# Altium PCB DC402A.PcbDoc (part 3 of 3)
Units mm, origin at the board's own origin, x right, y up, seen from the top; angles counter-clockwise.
Board outline 93 x 73 mm, 4 copper layers (Top Layer, Int1 (GND), Int2 (PWR), Bottom Layer), stack 1.369 mm thick; 244 components, 141 nets, 575 pads, 306 vias.
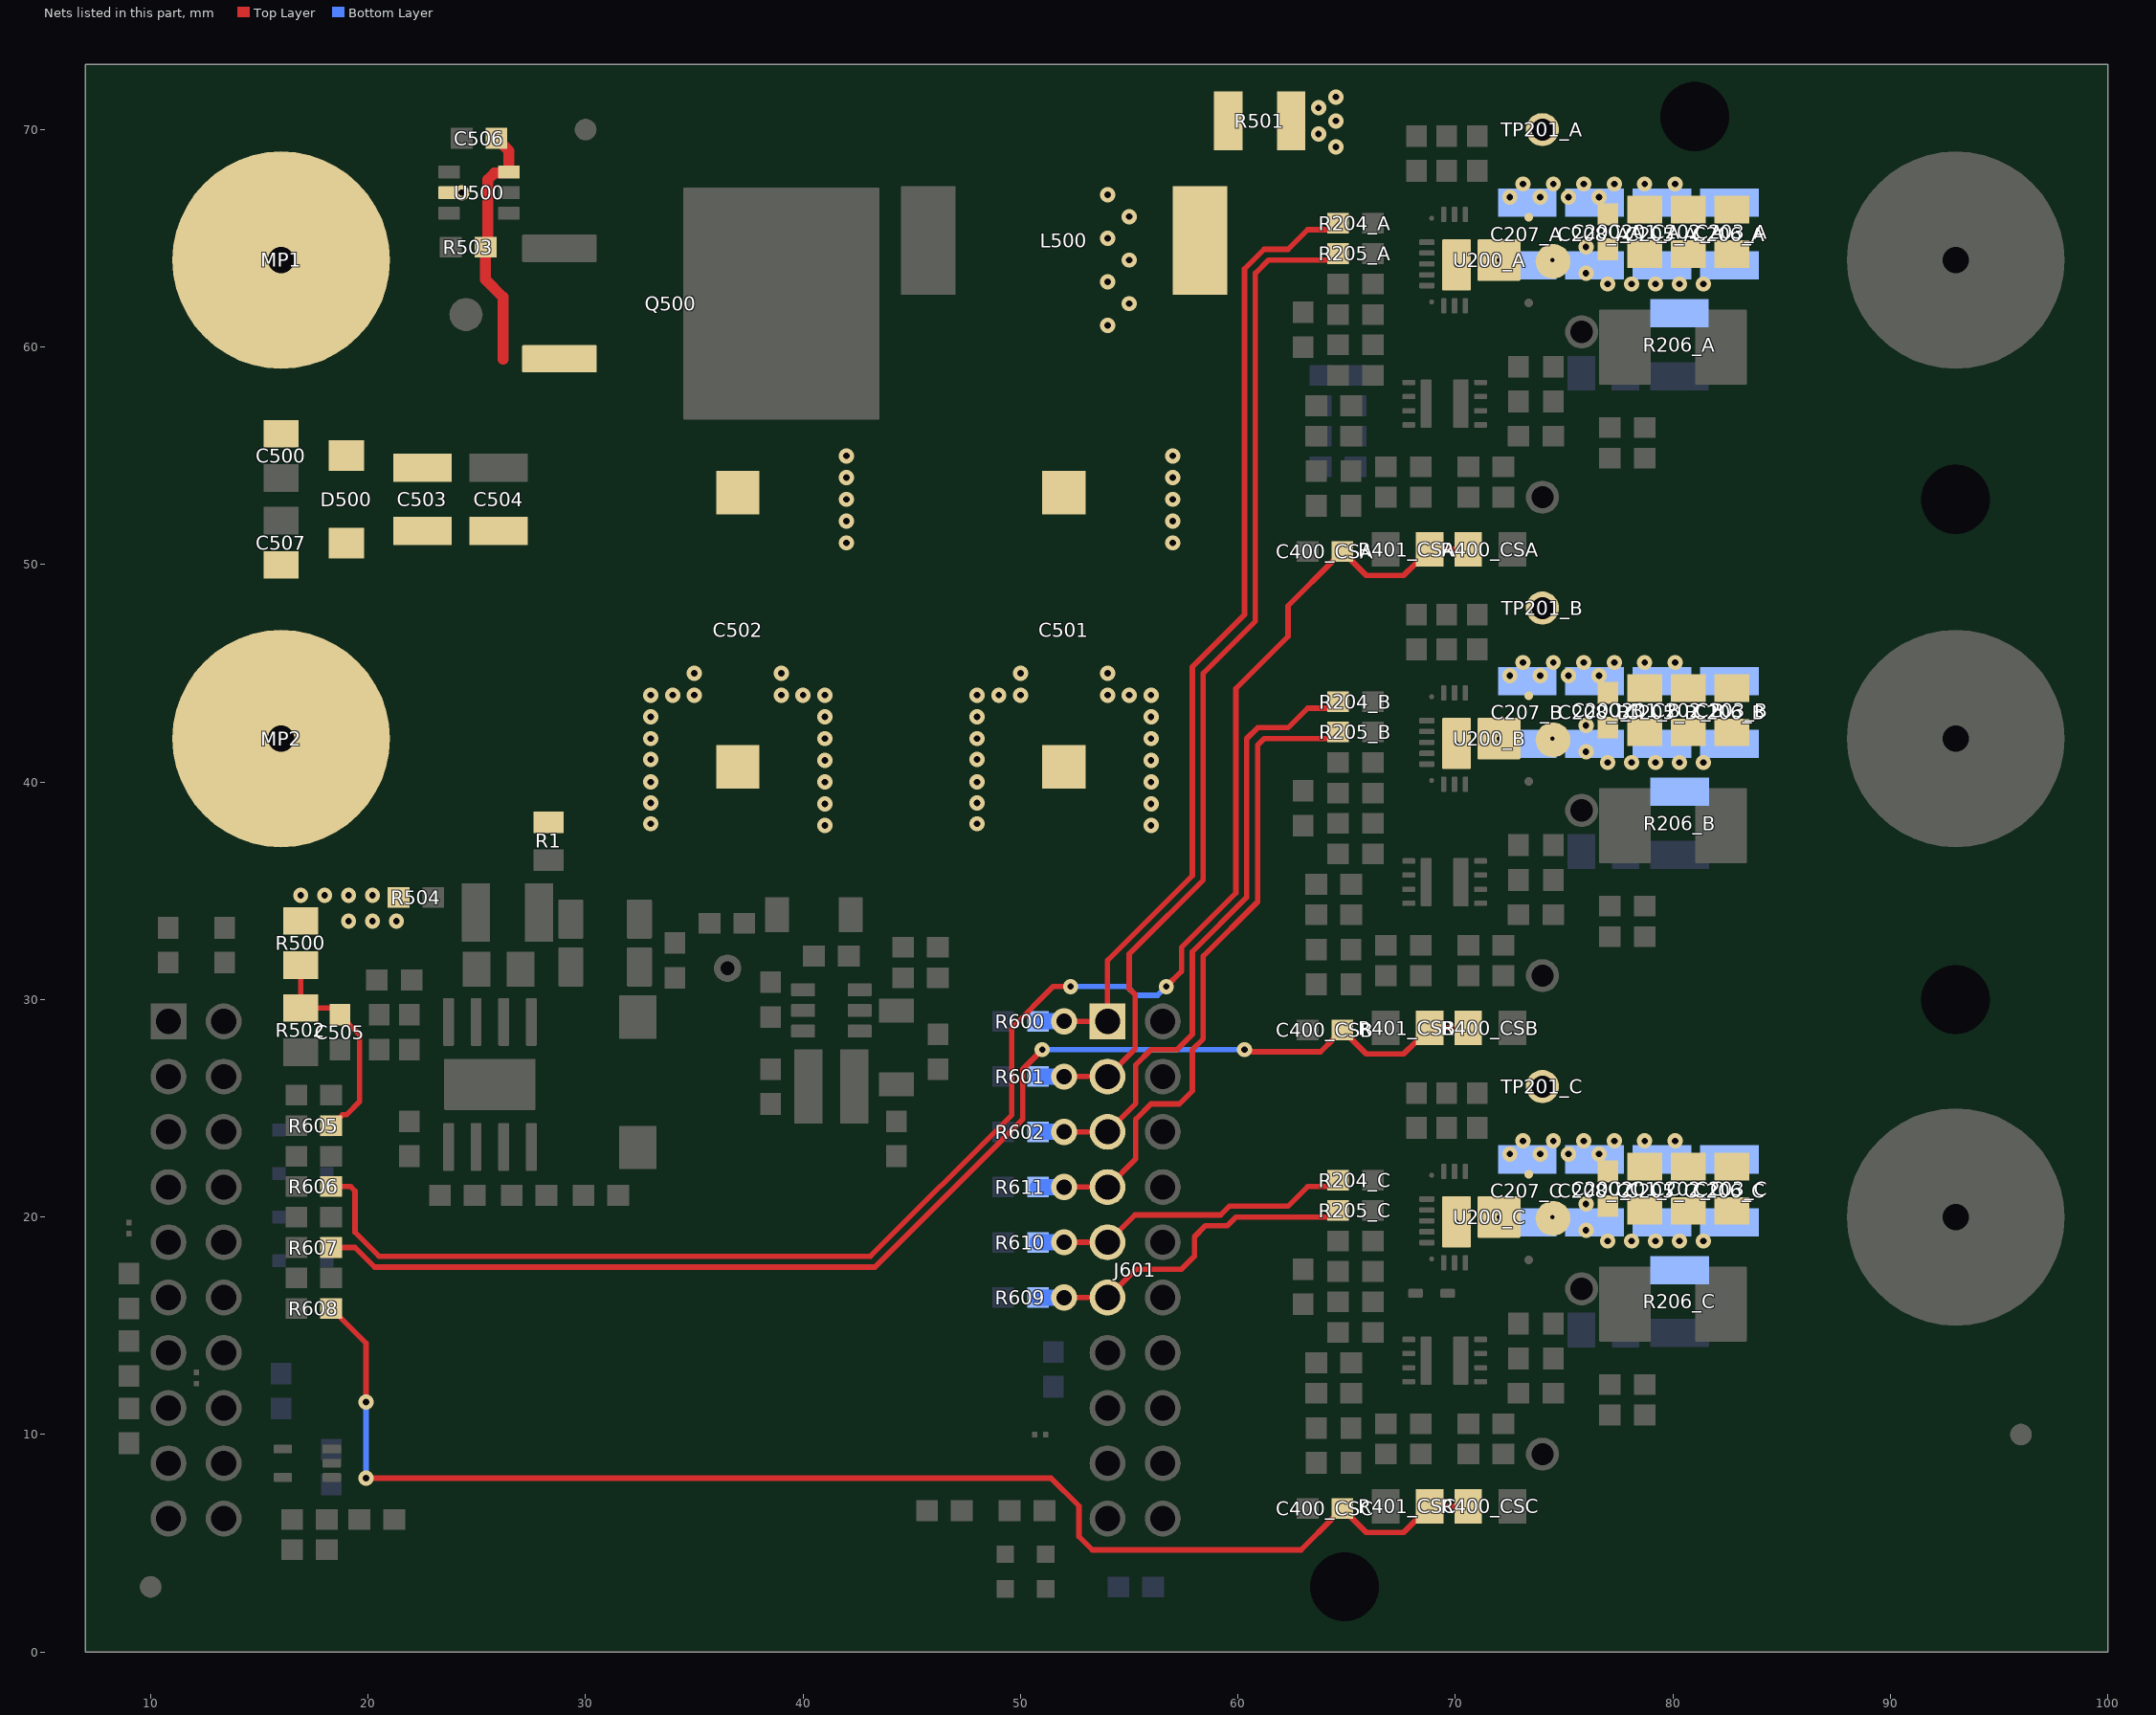
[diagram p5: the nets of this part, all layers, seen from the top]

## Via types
v1: diameter 0.7, hole 0.3, Top Layer to Bottom Layer, tented both sides, 277 vias
v2: diameter 1.2, hole 0.7, Top Layer to Bottom Layer, 10 vias
v3: diameter 0.5, hole 0.2, Top Layer to Bottom Layer, tented both sides, 9 vias
v4: diameter 0.7, hole 0.3, Top Layer to Bottom Layer, 9 vias
v5: diameter 1.2, hole 0.7, Top Layer to Bottom Layer, tented bottom, 1 vias

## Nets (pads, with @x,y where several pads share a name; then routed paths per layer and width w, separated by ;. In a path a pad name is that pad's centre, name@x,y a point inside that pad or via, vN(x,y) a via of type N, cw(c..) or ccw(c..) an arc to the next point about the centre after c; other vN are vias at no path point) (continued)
PGND: C200_A.2 C200_B.2 C200_C.2 C201_A.2 C201_B.2 C201_C.2 C202_A.2 C202_B.2 C202_C.2 C203_A.2 C203_B.2 C203_C.2 C205_A.2 C205_B.2 C205_C.2 C206_A.2 C206_B.2 C206_C.2 C207_A.2 C207_B.2 C207_C.2 C208_A.2 C208_B.2 C208_C.2 C501.2 C502.2 C503.2 C504.2 C507.2 D500.1 MP2.1 R1.1 R206_A.1 R206_B.1 R206_C.1 R501.1 TP201_A.1 TP201_B.1 TP201_C.1 U200_A.6 U200_B.6 U200_C.6 U500.2 | length 0.6
  Top Layer w0.5: U500.2@23.725,67.1 v1(24.3,67.1)
  other v1: 77,18.9 78.1,18.9 79.2,18.9 80.3,18.9 81.4,18.9 76,19.4 76,20.6 41,38 56,38 33,38.084 48,38.084 41,39 56,39 33,39.042 48,39.042 33,40 41,40 48,40 56,40 77,40.9 78.1,40.9 79.2,40.9 80.3,40.9 81.4,40.9 41,41 56,41 33,41.042 48,41.042 76,41.4 33,42 41,42 48,42 56,42 76,42.6 33,43 41,43 48,43 56,43 33,44 34,44 35,44 39,44 40,44 41,44 48,44 49,44 50,44 54,44 55,44 56,44 35,45 39,45 50,45 54,45 77,62.9 78.1,62.9 79.2,62.9 80.3,62.9 81.4,62.9 76,63.4 76,64.6 64.5,69.2 63.7,69.8 64.5,70.4 63.7,71 64.5,71.5
  other v3: 70.047,19.775 72,20 74.447,20 70.047,41.775 72,42 74.447,42 70.047,63.775 72,64 74.447,64
PWM_AH: J601.1 R204_A.1 R600.1 | length 45.6
  Top Layer w0.25: v2(52,29) J601.1@54,29 54,31.8 57.9,35.7 57.9,45.3 60.3,47.7 60.3,63.6 61.2,64.5 62.3,64.5 63.2,65.4 64.3,65.4 R204_A.1@64.6,65.7
  Bottom Layer w0.75: R600.1@50.8,29 v2(52,29)
PWM_AL: J601.3 R205_A.1 R601.1 | length 47.4
  Top Layer w0.25: v2(52,26.46) J601.3@54,26.46 55.27,27.73 55.27,30.23 55,30.5 55,32.1 55.27,32.37 58.4,35.5 58.4,45 60.8,47.4 60.8,63.4 61.4,64 64.275,64 64.575,64.3 R205_A.1@64.6,64.3
  Bottom Layer w0.75: R601.1@50.8,26.46 v2(52,26.46)
PWM_BH: J601.5 R204_B.1 R602.1 | length 29.5
  Top Layer w0.25: v2(52,23.92) J601.5@54,23.92 55.3,25.22 55.3,27 56,27.7 57.2,27.7 57.9,28.4 57.9,32.2 60.4,34.7 60.4,34.973 60.4,42 60.9,42.5 62.3,42.5 63.2,43.4 64.3,43.4 R204_B.1@64.6,43.7
  Bottom Layer w0.75: R602.1@50.8,23.92 v2(52,23.92)
PWM_BL: J601.7 R205_B.1 R611.2 | length 31.1
  Top Layer w0.25: v2(52,21.38) J601.7@54,21.38 55.3,22.68 55.3,24.5 56,25.2 57.3,25.2 57.9,25.8 57.9,27.7 58.4,28.2 58.4,32 60.9,34.5 60.9,41.7 61.2,42 64.275,42 64.575,42.3 R205_B.1@64.6,42.3
  Bottom Layer w0.75: R611.2@50.8,21.38 v2(52,21.38)
PWM_CH: J601.9 R204_C.1 R610.2 | length 15
  Top Layer w0.25: v2(52,18.84) J601.9@54,18.84 55.26,20.1 59.2,20.1 59.6,20.5 62.3,20.5 63.2,21.4 64.3,21.4 R204_C.1@64.6,21.7
  Bottom Layer w0.75: R610.2@50.8,18.84 v2(52,18.84)
PWM_CL: J601.11 R205_C.1 R609.2 | length 16
  Top Layer w0.25: v2(52,16.3) J601.11@54,16.3 55.3,17.6 57.4,17.6 58,18.2 58,19.1 58.5,19.6 59.5,19.6 59.9,20 64.275,20 64.575,20.3 R205_C.1@64.6,20.3
  Bottom Layer w0.75: R609.2@50.8,16.3 v2(52,16.3)
VBUS: C200_A.1 C200_B.1 C200_C.1 C201_A.1 C201_B.1 C201_C.1 C202_A.1 C202_B.1 C202_C.1 C203_A.1 C203_B.1 C203_C.1 C205_A.1 C205_B.1 C205_C.1 C206_A.1 C206_B.1 C206_C.1 C207_A.1 C207_B.1 C207_C.1 C208_A.1 C208_B.1 C208_C.1 C501.1 C502.1 L500.2 R500.1 R501.2 R504.2 U200_A.7 U200_B.7 U200_C.7
  other v1: 72.5,22.9 73.9,22.9 75.2,22.9 76.6,22.9 73.1,23.5 74.5,23.5 75.9,23.5 77.3,23.5 78.7,23.5 80.1,23.5 19.1,33.6 20.2,33.6 21.3,33.6 16.9,34.8 18,34.8 19.1,34.8 20.2,34.8 72.5,44.9 73.9,44.9 75.2,44.9 76.6,44.9 73.1,45.5 74.5,45.5 75.9,45.5 77.3,45.5 78.7,45.5 80.1,45.5 42,51 57,51 42,52 57,52 42,53 57,53 42,54 57,54 42,55 57,55 54,61 55,62 54,63 55,64 54,65 55,66 72.5,66.9 73.9,66.9 75.2,66.9 76.6,66.9 54,67 73.1,67.5 74.5,67.5 75.9,67.5 77.3,67.5 78.7,67.5 80.1,67.5
VCC48: C500.1 C503.1 C506.1 D500.2 MP1.1 Q500.3 R503.2 U500.6 | length 11.6
  Top Layer w0.5: C506.1@25.9,69.6 25.925,69.6 26.15,69.375 26.15,69.35 26.475,69.025 U500.6@26.475,68.05 26.425,68 25.801,68 25.508,67.707 25.508,64.708 R503.2@25.4,64.6 25.4,63.1 26.2,62.3 26.2,59.437
VSNS_DC: C505.1 R500.2 R502.2 R605.2 | length 10
  Top Layer w0.25: R500.2@16.9,31.584 R502.2@16.9,29.616 18.359,29.616 19.05,28.925 19.075,28.925 19.6,28.4 19.6,25.3 19,24.7 18.821,24.7 18.675,24.554 18.675,24.55 18.325,24.2 R605.2@18.3,24.2
VSNS_phA: C400_CSA.1 R400_CSA.2 R401_CSA.2 R606.2 | length 78.9
  Top Layer w0.25: R606.2@18.3,21.4 19.2,21.4 19.4,21.2 19.4,19.3 20.5,18.2 43.1,18.2 49.6,24.7 49.6,28.7 51.5,30.6 v1(52.3,30.6) ; v1(56.7,30.6) 57.4,31.3 57.4,32.4 59.9,34.9 59.9,44.3 62.3,46.7 62.3,48.1 64.425,50.225 64.425,50.25 64.775,50.6 C400_CSA.1@64.8,50.6 64.825,50.6 65.175,50.25 65.175,50.225 65.9,49.5 67.616,49.5 68.141,50.025 68.306,50.025 68.816,50.535 R401_CSA.2@68.816,50.7 R400_CSA.2@70.584,50.7
  Bottom Layer w0.25: v1(52.3,30.6) 54.9,30.6 55.3,30.2 56.3,30.2 v1(56.7,30.6)
VSNS_phB: C400_CSB.1 R400_CSB.2 R401_CSB.2 R607.2 | length 59.1
  Top Layer w0.25: R607.2@18.3,18.6 19.4,18.6 20.3,17.7 43.3,17.7 50.1,24.5 50.1,26.8 v1(51,27.7) ; v1(60.3,27.7) 60.386,27.614 60.658,27.614 60.671,27.6 63.8,27.6 64.425,28.225 64.425,28.25 64.775,28.6 C400_CSB.1@64.8,28.6 ; C400_CSB.1@65.175,28.225 65.9,27.5 67.616,27.5 68.141,28.025 68.306,28.025 68.816,28.535 R401_CSB.2@68.816,28.7 R400_CSB.2@70.584,28.7
  Bottom Layer w0.25: v1(51,27.7) v1(60.3,27.7)
VSNS_phC: C400_CSC.1 R400_CSC.2 R401_CSC.2 R608.2 | length 62.7
  Top Layer w0.25: R608.2@18.3,15.8 19.9,14.2 v1(19.9,11.5) ; v1(19.9,8) 20.7,8 50,8 51.4,8 52.685,6.715 52.685,5.315 53.3,4.7 62.9,4.7 64.425,6.225 64.425,6.25 64.775,6.6 C400_CSC.1@64.8,6.6 ; C400_CSC.1@65.175,6.225 65.9,5.5 67.616,5.5 68.141,6.025 68.306,6.025 68.816,6.535 R401_CSC.2@68.816,6.7 R400_CSC.2@70.584,6.7
  Bottom Layer w0.25: v1(19.9,8) v1(19.9,11.5)
pads on no net: FID300.1 FID301.1 FID302.1 LBL300.0 MH1.1 MH2.1 MH3.1 MH4.1

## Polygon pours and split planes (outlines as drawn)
DGND on Int1 (GND) "INT1_(GND)_DGND_P006" (solid, remove dead copper, pour order 6): 8,33.8 8,1 57.3,1 57.3,33.8
PGND on Int1 (GND) "Int1 (GND)-PGND" (solid, remove dead copper, pour order 2): 59,5 99,5 99,72 8,72 8,36 59,36
VBUS on Int2 (PWR) "Int2 (PWR)-VBUS" (solid, remove dead copper, pour order 8): 16.1,32.981 29.981,32.981 33,36 59,36 59,21.681 99,21.681 99,72 57.5,72 53,67.5 53,62 47,56 33,56 25,48 25,37.5 22.85,35.35 16.1,35.35
DGND on Bottom Layer "BOTTOM_LAYER_DGND_P004" (solid, remove dead copper, pour order 4): 8,33.7 61,33.7 61,68.7 69,68.7 69,1 8,1
NetC515_1 on Top Layer "TOP_LAYER_NETC515_1_P005" (solid, remove dead copper, pour order 5): 36.8,34.7 41.1,34.7 41.1,29.2 38.975,29.2 38.975,28.7 35.1,28.7 35.1,32.7 36.8,32.7 36.8,34.375

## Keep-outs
Keep-Out Layer:
  text ".Layer_Name" at 14.656,-21.806 h1.52

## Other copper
Top Layer:
  region net INP_CSB: 69.9,30.625 70.6,30.625 71.1,30.625 71.1,32.975 70.6,33.475 70.6,34.334 70.6,35.95 70.9,36.25 71.45,36.25 71.8,36.6 72.425,36.6 75,36.6 75.7,35.9 78.98,35.9 78.98,39.725 75.248,39.725 75.248,40.2 ccw(c75.198,40.2) 75.198,40.25 71.54,40.25 ccw(c71.54,40.2) 71.49,40.2 71.49,38.076 69.9,36.486 69.9,34.334
  region net AVDD_CSB: 72.7,30.625 72.7,32.975 72.325,32.975 71.6,33.7 71.6,34.371 71.421,34.55 70.9,34.55 ccw(c70.9,34.5) 70.865,34.535 ccw(c70.9,34.5) 70.85,34.5 70.85,33.75 71.7,32.9 71.7,30.625
  region net INP_CSC: 69.9,8.625 70.6,8.625 71.1,8.625 71.1,10.975 70.6,11.475 70.6,12.334 70.6,13.95 70.9,14.25 71.45,14.25 71.8,14.6 72.425,14.6 75,14.6 75.7,13.9 78.98,13.9 78.98,17.725 75.248,17.725 75.248,18.2 ccw(c75.198,18.2) 75.198,18.25 71.54,18.25 ccw(c71.54,18.2) 71.49,18.2 71.49,16.076 69.9,14.486 69.9,12.334
  region net AVDD_CSC: 72.7,8.625 72.7,10.975 72.325,10.975 71.6,11.7 71.6,12.371 71.421,12.55 70.9,12.55 ccw(c70.9,12.5) 70.865,12.535 ccw(c70.9,12.5) 70.85,12.5 70.85,11.75 71.7,10.9 71.7,8.625
  region net AVDD_CSA: 72.7,52.625 72.7,54.975 72.325,54.975 71.6,55.7 71.6,56.371 71.421,56.55 70.9,56.55 ccw(c70.9,56.5) 70.865,56.535 ccw(c70.9,56.5) 70.85,56.5 70.85,55.75 71.7,54.9 71.7,52.625
  region net INP_CSA: 69.9,52.625 70.6,52.625 71.1,52.625 71.1,54.975 70.6,55.475 70.6,56.334 70.6,57.95 70.9,58.25 71.45,58.25 71.8,58.6 72.425,58.6 75,58.6 75.7,57.9 78.98,57.9 78.98,61.725 75.248,61.725 75.248,62.2 ccw(c75.198,62.2) 75.198,62.25 71.54,62.25 ccw(c71.54,62.2) 71.49,62.2 71.49,60.076 69.9,58.486 69.9,56.334
  region net PGND: 25.53,35.999 27.185,37.655 29.428,37.655 31.084,35.999 57,35.965 57,45.5 28,45.5 28,52.2 18.7,52.2 17.119,50.619 8,50.619 8,35.961
  region net DGND: 20,28.2 22.4,28.2 23.325,27.275 26.975,27.275 27.255,27.555 27.255,30.361 26.5,31.116 26.5,35.815 27.6,36.915 29,36.915 29.9,36.015 29.9,24.925 23.4,24.925 22.375,23.9 20.8,23.9 20.025,24.675
  region net VBUS: 21.9,34.225 21.9,33.2 21.681,32.981 16.1,32.981 16.1,35.35 21.9,35.35
  region net P5V: 33.625,32.1 34.8,32.1 34.8,33 36.2,33 36.2,35.4 33.6,35.4
  region net VBUS: 33,48.5 59.5,48.5 59.5,68.7 60.2,68.7 60.2,72 57.5,72 53,67.5 53,62 47,56 33,56
  region net PGND: 61.8,72 65,72 65,68.7 61.8,68.7
  region net NetC509_1: 25.215,28.975 25.215,30.215 25.619,30.619 25.619,35.35 22.5,35.35 22.5,31.375 21.5,31.375 21.5,30.7 24.2,30.7 24.715,30.185 24.715,28.975
  region net NetC508_2: 27.255,24.325 33.25,24.325 33.25,22.2 29.425,22.2 28.7,21.475 28.7,20.525 27.7,20.525 27.7,21.475 27.255,21.92
  region net NetC511_2: 31.55,28 34.8,28 34.8,31.6 33.1,31.6 33.1,34.6 31.55,34.6 31.55,28.841
  region net INN_CSB: 81.02,39.725 85,39.725 85,48.1 99.1,48.1 99.1,35.9 81.02,35.9
  region net VBUS: 71.49,43.681 71.49,44.59 72.9,46 84,46 84,43.681
  region net PGND: 84,42.95 84,40.475 76.843,40.475 76.268,41.05 71.146,41.05 70.696,40.6 69.435,40.6 69.435,42.95
  region net DGND: 65.7,37.625 66.7,37.625 67.4,36.925 67.4,36.4 67.55,36.25 68.1,36.25 68.4,35.95 68.4,33.9 67.9,33.4 67.9,30.625 68.9,30.625 68.9,37.2 68,38.1 68,40.9 67.6,40.9 66.675,39.975 65.7,39.975
  region net P3V3: 66.3,30.625 66.3,33.6 67.25,34.55 67.85,34.55 67.85,34.3 67.3,33.75 67.3,30.625
  region net NetC513_2: 40.9,24.3 40.9,28.2 40.55,28.55 39.275,28.55 38.025,27.3 38.025,26.3 39.3,26.3 39.6,26 39.6,24.3
  region net NetC514_1: 41.7,24.3 43.425,24.3 43.825,23.9 44.775,23.9 46.675,25.8 46.675,26.35 45.325,27.7 41.7,27.7
  region net DGND: 42.6,29.8 43.25,29.8 43.5,30.05 43.5,30.8 42.775,31.525 41.6,31.525 41.6,34.7 45.1,34.7 45.1,28.95 43.5,28.95 43.25,29.2 42.6,29.2
  region net NetC504_1: 47,67.5 47,58.5 45.166,56.666 33,56.666 33,67.5
  region net VCC48: 23.85,53.8 23.85,55.75 26.932,58.832 30.515,58.832 30.515,60.089 22.912,60.089 22.035,60.965 22.035,66.2 22.035,67.2 22.035,70.035 8,70.035 8,55.381 17.114,55.381 18.695,53.8 22.5,53.8
  region net INN_CSC: 81.02,17.725 85,17.725 85,26.1 99.1,26.1 99.1,13.9 81.02,13.9
  region net VBUS: 71.49,21.681 71.49,22.59 72.9,24 84,24 84,21.681
  region net PGND: 84,20.95 84,18.475 76.843,18.475 76.268,19.05 71.146,19.05 70.696,18.6 69.435,18.6 69.435,20.95
  region net DGND: 65.7,15.625 66.7,15.625 67.4,14.925 67.4,14.4 67.55,14.25 68.1,14.25 68.4,13.95 68.4,11.9 67.9,11.4 67.9,8.625 68.9,8.625 68.9,15.2 68,16.1 68,18.9 67.6,18.9 66.675,17.975 65.7,17.975
  region net P3V3: 66.3,8.625 66.3,11.6 67.25,12.55 67.85,12.55 67.85,12.3 67.3,11.75 67.3,8.625
  region net P3V3: 66.3,52.625 66.3,55.6 67.25,56.55 67.85,56.55 67.85,56.3 67.3,55.75 67.3,52.625
  region net DGND: 65.7,59.625 66.7,59.625 67.4,58.925 67.4,58.4 67.55,58.25 68.1,58.25 68.4,57.95 68.4,55.9 67.9,55.4 67.9,52.625 68.9,52.625 68.9,59.2 68,60.1 68,62.9 67.6,62.9 66.675,61.975 65.7,61.975
  region net PGND: 84,64.95 84,62.475 76.843,62.475 76.268,63.05 71.146,63.05 70.696,62.6 69.435,62.6 69.435,64.95
  region net VBUS: 71.49,65.681 71.49,66.59 72.9,68 84,68 84,65.681
  region net INN_CSA: 81.02,61.725 85,61.725 85,70.1 99.1,70.1 99.1,57.9 81.02,57.9
  text ".Layer_Name" at 14.656,-21.806 h1.52
Bottom Layer:
  region net INN_CSC: 99,26.035 99,13.965 86.93,13.965 86.93,26.035
  region net INN_CSB: 99,48.035 99,35.965 86.93,35.965 86.93,48.035
  region net INN_CSA: 99,70.035 99,57.965 86.93,57.965 86.93,70.035
  region net VBUS: 71.49,43.681 71.49,44.89 72.6,46 84,46 84,43.681
  region net PGND: 72.419,41.05 76.268,41.05 78.41,38.908 84,38.908 84,42.95 69.435,42.95 69.435,41.05
  region net VBUS: 71.49,21.681 71.49,22.89 72.6,24 84,24 84,21.681
  region net PGND: 72.419,19.05 76.268,19.05 78.402,16.916 84,16.916 84,20.95 69.435,20.95 69.435,19.05
  region net PGND: 72.419,63.05 76.268,63.05 78.418,60.9 84,60.9 84,64.95 69.435,64.95 69.435,63.05
  region net VBUS: 71.49,65.681 71.49,66.89 72.6,68 84,68 84,65.681
  text ".Layer_Name" at 14.656,-21.806 h1.52

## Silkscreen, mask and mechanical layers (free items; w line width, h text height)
Top Overlay:
  circle w0.2: c61.5,46 r0.5
  circle w0.2: c61.5,68 r0.5
  circle w0.2: c61.5,24 r0.5
  lines w0.15: 41.65,27.975 42.375,27.975 42.5,28.1 ; 44.524,20.566 44.998,20.566 46,21.567 46,22.2
  lines w0.2: 61,24 62,24 ; 61,46 62,46 ; 61,68 62,68 ; 61.5,23.5 61.5,24.5 ; 61.5,45.5 61.5,46.5 ; 61.5,67.5 61.5,68.5 ; 66.9,23.4 66.9,23.1 67.2,22.8 67.2,22.2 ; 66.9,45.4 66.9,45.1 67.2,44.8 67.2,44.2 ; 66.9,67.4 66.9,67.1 67.2,66.8 67.2,66.2 ; 67.2,20.8 67.2,21.2 ; 67.2,42.8 67.2,43.2 ; 67.2,64.8 67.2,65.2
  text "+VIN" at 13.901,70.4 h1.2
  text "PGND" at 75.152,69.652 h0.7
  text "PWMH" at 64.152,68.852 h0.7
  text "PWML" at 64.152,67.752 h0.7
  text "SW" at 73.652,60.352 h0.7
  text "PHASE A" at 85.578,60.001 h1.2 r90
  text "DGND" at 59.352,58.452 h0.7
  text "D" at 61.452,56.952 h0.7
  text "C" at 61.452,55.542 h0.7
  text "AVDD" at 75.052,52.752 h0.7
  text "PGND" at 75.152,47.652 h0.7
  text "PWMH" at 64.152,46.852 h0.7
  text "PWML" at 64.152,45.752 h0.7
  text "-VIN" at 24.6,39.901 h1.2 r90
  text "SW" at 73.652,38.352 h0.7
  text "PHASE B" at 85.578,38.001 h1.2 r90
  text "P5V" at 12.7,34.4 h0.7
  text "AVDD" at 75.052,30.752 h0.7
  text "PWM_AH" at 47.2,28.7 h0.7
  text "PWM_AL" at 47.2,26.16 h0.7
  text "PGND" at 75.152,25.652 h0.7
  text "PWMH" at 64.152,24.852 h0.7
  text "PWML" at 64.152,23.752 h0.7
  text "PWM_BH" at 47.2,23.62 h0.7
  text "DC" at 8.307,23.552 h0.7
  text "VI" at 14.484,23.529 h0.7
  text "P3V3" at 39.4,22.4 h0.7
  text "PWM_BL" at 47.2,21.08 h0.7
  text "CC" at 8.307,21.012 h0.7
  text "VA" at 14.484,21 h0.7
  text "DGND" at 41.7,20.267 h0.7
  text "PWM_CH" at 47.2,18.54 h0.7
  text "VB" at 14.484,18.449 h0.7
  text "SW" at 73.652,16.352 h0.7
  text "PWM_CL" at 47.2,16 h0.7
  text "PHASE C" at 85.578,16.001 h1.2 r90
  text "VC" at 14.484,15.909 h0.7
  text "DA" at 57.664,15.909 h0.7
  text "DGND" at 17.805,13.683 h0.7
  text "CA" at 57.664,13.369 h0.7
  text "DGND" at 42.505,11.683 h0.7
  text "Rev. A" at 39.127,9.152 h0.7
  text "AVDD" at 75.052,8.752 h0.7
  text "CB" at 8.307,7.7 h0.7
  text "BP_AMC0106-LMG-MD" at 23.101,7.5 h1.2
  text "DB" at 8.307,5.772 h0.7
  text "P5V" at 48.048,2.652 h0.7 r90
  text "P3V3" at 52.948,2.652 h0.7 r90
  text ".Layer_Name" at 14.656,-21.806 h1.52
Bottom Overlay:
  text ".Layer_Name" at 14.656,-21.806 h1.52
Top Paste:
  text ".Layer_Name" at 14.656,-21.806 h1.52
Bottom Paste:
  text ".Layer_Name" at 14.656,-21.806 h1.52
Top Solder:
  region: 8,50.619 13.4,50.619 13.4,48.035 22.035,48.035 22.035,35.965 8,35.965
  region: 8,55.381 13.4,55.381 13.4,57.965 22.035,57.965 22.035,70.035 8,70.035
  region: 99.035,26.035 99.035,13.965 86.965,13.965 86.965,26.035
  region: 99.035,48.035 99.035,35.965 86.965,35.965 86.965,48.035
  region: 99.035,70.035 99.035,57.965 86.965,57.965 86.965,70.035
  text ".Layer_Name" at 14.656,-21.806 h1.52
  text ".Layer_Name" at 14.656,-21.806 h1.52
Bottom Solder:
  region: 99.07,26.035 99.07,13.965 87,13.965 87,26.035
  region: 99.07,48.035 99.07,35.965 87,35.965 87,48.035
  region: 99.07,70.035 99.07,57.965 87,57.965 87,70.035
  text ".Layer_Name" at 14.656,-21.806 h1.52
Drill Guide:
  text ".Layer_Name" at 14.656,-21.806 h1.52
M1 Board Outline:
  the board outline again, w0.254
  text ".Layer_Name" at 14.656,-21.806 h1.52
M2 Board Dimensions:
  rectangle: 0,-6.985 3.175,-3.81
  rectangle: 3.175,-10.16 12.7,-6.985
  lines w0.178: 0,-6.985 25.4,-6.985 ; 3.175,-10.16 3.175,-3.81 ; 6.35,-10.16 6.35,-3.81 ; 12.7,-10.16 12.7,-3.81 ; 19.05,-10.16 19.05,-3.81 ; 0,-10.16 25.4,-10.16 25.4,-3.81 0,-3.81 0,-10.16
  text ".Layer_Name" at 14.656,-21.806 h1.52
M3 3D STEP Top:
  text ".Layer_Name" at 14.656,-21.806 h1.52
M4 3D STEP Bottom:
  text ".Layer_Name" at 14.656,-21.806 h1.52
M5 Assembly Top:
  lines w0.254: -7.417,-23.626 160.223,-23.626 ; -7.417,-18.462 160.274,-18.462 ; -7.417,-13.297 -7.417,-28.791 94.31,-28.791 160.274,-28.791 160.274,-13.297 -7.404,-13.297 -7.404,-28.791 32.614,-28.791 ; 55.194,-28.791 55.194,-13.297 ; 87.376,-18.462 87.376,-13.297 ; 108.712,-18.462 108.712,-13.297 ; 124.511,-28.956 124.511,-23.804
  text "COMPONENTS MARKED 'DNP' SHOULD NOT BE POPULATED." at 29.299,-8.09 h1.52
  text "ASSEMBLY VARIANT:" at 29.286,-11.024 h1.52
  text ".VariantName" at 55.601,-11.024 h1.52
  text "PCB VIEWED FROM TOP SIDE" at -5.804,-16.654 h1.52
  text "BOARD #:" at 57.099,-16.654 h1.52
  text ".PRJ_Number" at 70.955,-16.654 h1.52
  text "REV:" at 92.405,-16.654 h1.52
  text ".PCB_Rev" at 99.809,-16.654 h1.52
  text "SVN REV:" at 113.69,-16.654 h1.52
  text ".VersionControl_RevNumber" at 126.543,-16.654 h1.52
  text "TID #:" at 57.099,-21.819 h1.52
  text ".TID" at 70.955,-21.819 h1.52
  text "PLOT NAME =" at -5.804,-27.034 h1.52
  text ".plot_File_Name" at 14.656,-27.034 h1.52
  text "GENERATED    :" at 57.15,-27.034 h1.52
  text ".Print_Date" at 79.235,-27.034 h1.52
  text ".Print_Time" at 97.752,-27.034 h1.52
  text "TEXAS INSTRUMENTS" at 129.87,-27.034 h1.52
M6 Assembly Bottom:
  lines w0.254: -7.429,-18.474 160.261,-18.474 ; -7.379,-23.639 160.261,-23.639 ; 28.334,-28.969 28.334,-23.817 ; 44.133,-18.474 44.133,-13.31 ; 65.468,-18.474 65.468,-13.31 ; 97.65,-28.804 97.65,-13.31 ; 120.231,-28.804 160.249,-28.804 160.249,-13.31 -7.429,-13.31 -7.429,-28.804 58.534,-28.804 160.261,-28.804 160.261,-13.31
  text "COMPONENTS MARKED 'DNP' SHOULD NOT BE POPULATED." at 154.991,-8.077 h1.52
  text ".VariantName" at 128.473,-11.024 h1.52
  text "ASSEMBLY VARIANT:" at 154.864,-11.024 h1.52
  text ".VersionControl_RevNumber" at 26.302,-16.667 h1.52
  text "SVN REV:" at 39.154,-16.667 h1.52
  text ".PCB_Rev" at 53.035,-16.667 h1.52
  text "REV:" at 60.439,-16.667 h1.52
  text ".PRJ_Number" at 81.89,-16.667 h1.52
  text "BOARD #:" at 95.745,-16.667 h1.52
  text "PCB VIEWED FROM BOTTOM SIDE" at 158.648,-16.667 h1.52
  text ".TID" at 81.89,-21.831 h1.52
  text "TID #:" at 95.745,-21.831 h1.52
  text "TEXAS INSTRUMENTS" at 22.974,-27.047 h1.52
  text ".Print_Time" at 55.093,-27.047 h1.52
  text ".Print_Date" at 73.609,-27.047 h1.52
  text "GENERATED    :" at 95.694,-27.047 h1.52
  text ".plot_File_Name" at 138.189,-27.047 h1.52
  text "PLOT NAME =" at 158.648,-27.047 h1.52
M9 Title Sheet:
  drawing of 57 lines, arcs and shapes, not listed
  text "1" at 18.792,204.127 h1.78
  text "2" at 82.182,204.127 h1.78
  text "3" at 145.411,204.127 h1.78
  text "4" at 209.08,204.127 h1.78
  text "5" at 272.555,204.127 h1.78
  text "6" at 336.182,204.127 h1.78
  text "A" at -10.579,175.095 h1.78
  text "A" at 365.341,175.095 h1.78
  text "B" at -10.579,114.643 h1.78
  text "B" at 365.341,114.643 h1.78
  text "C" at -10.579,54.318 h1.78
  text "C" at 365.341,54.318 h1.78
  text "PROJECT TITLE:" at 288.125,7.048 h1.14
  text ".PRJ_Title" at 289.395,3.662 h1.78
  text "DESIGNED FOR:" at 288.125,-0.597 h1.14
  text ".PRJ_Customer" at 289.395,-4.153 h1.78
  text "D" at -10.579,-5.88 h1.78
  text "D" at 365.341,-5.88 h1.78
  text "FILE NAME:" at 288.125,-8.217 h1.14
  text ".PCB_File_Name_No_Path" at 289.395,-11.265 h1.78
  text "Texas Instruments (TI) and/or its licensors do not warrant the accuracy or completeness of this specification" at 161.9,-15.376 h1.14
  text "ENGINEER:" at 288.125,-15.583 h1.14
  text "LAYOUT BY:" at 326.352,-15.583 h1.14
  text "or any information contained therein. TI and/or its licensors do not warrant that this design will meet" at 160.757,-18.237 h1.14
  text ".PRJ_Engineer" at 289.395,-19.52 h1.78
  text ".PCB_Layout" at 327.635,-19.52 h1.78
  text "the specifications, will be suitable for your application or fit for any particular purpose, or will operate in" at 160.757,-21.099 h1.14
  text ".Layer_Name" at 14.656,-21.806 h1.52
  text "ALTIUM DESIGNER VERSION:" at 326.352,-23.457 h1.14
  text "an implementation. TI and/or its licensors do not warrant that the design is production worthy. You should" at 160.757,-23.961 h1.14
  text "completely validate and test your design implementation to confirm the system functionality for your application." at 161.9,-26.822 h1.14
  text ".print_Scale" at 289.395,-26.843 h1.78
  text ".Application_BuildNumber" at 327.635,-26.843 h1.78
  text "1" at 18.792,-32.093 h1.78
  text "2" at 82.182,-32.093 h1.78
  text "3" at 145.411,-32.093 h1.78
  text "4" at 209.08,-32.093 h1.78
  text "5" at 272.555,-32.093 h1.78
  text "6" at 336.182,-32.093 h1.78
M10 Fab Notes:
  drawing of 189 lines, arcs and shapes, not listed
  text "DESIGN INFORMATION" at 314.503,161.447 h1.52
  text "MIN. TRACK WIDTH:" at 298.131,158.091 h1.52
  text "8" at 325.976,158.091 h1.52
  text "MIL" at 329.907,158.091 h1.52
  text "7.874" at 321.75,155 h1.52
  text "MIN. CLEARANCE:" at 298.131,154.938 h1.52
  text "MIL" at 329.907,154.938 h1.52
  text "MIN. VIA PAD SIZE:" at 298.131,151.785 h1.52
  text "24" at 325.214,151.785 h1.52
  text "MIL" at 329.907,151.785 h1.52
  text "0.05mm (2MIL)" at 315.784,148.486 h1.52
  text "MINIMUM ANNULAR RING" at 289.769,148.277 h1.52
  text "EXTERNAL" at 333.768,148.277 h1.52
  text "PER" at 294.849,145.48 h1.52
  text "IPC-D-275 CLASS 2 LEVEL C" at 300.437,145.48 h1.52
  text "MIL, HOLES" at 338.238,142.928 h1.52
  text "+/-" at 328.27,142.709 h1.52
  text "+/-" at 349.961,142.709 h1.52
  text "REGISTRATION TOLERANCES:" at 289.769,142.682 h1.52
  text "METAL" at 320.243,142.682 h1.52
  text "5" at 334.879,142.683 h1.52
  text "3" at 356.037,142.683 h1.52
  text "MIL" at 358.99,142.682 h1.52
  text "HOLE SIZE TOLERANCE (UNLESS OTHERWISE SPECIFIED):" at 289.769,140.185 h1.52
  text "+/-" at 349.961,140.112 h1.52
  text "3" at 356.037,140.085 h1.52
  text "MIL" at 358.99,140.085 h1.52
  text "MATERIAL:" at 287.87,136.589 h1.52
  text "FR-4 High Tg" at 312.926,133.324 h1.52
  text "X" at 309.257,133.122 h1.52
  text "FR-4" at 298.563,133.007 h1.52
  text "OTHER" at 336.358,133.007 h1.52
  text "62 MIL (1.6mm) +/-10%" at 306.694,129.374 h1.52
  text "X" at 303.643,129.312 h1.52
  text "THICKNESS:" at 289.769,129.165 h1.52
  text "OTHER" at 339.33,129.165 h1.52
  text "TOLERANCE:" at 289.769,125.652 h1.52
  text "X" at 311.314,125.652 h1.52
  text "ANSI IPC-6012 TYPE 3 CLASS 2" at 315.836,125.652 h1.52
  text "OTHER +/-" at 315.835,121.989 h1.52
  text "BOW & TWIST:" at 289.769,118.302 h1.52
  text "X" at 311.314,118.302 h1.52
  text "ANSI IPC-6012 TYPE 3 CLASS 2" at 315.836,118.302 h1.52
  text "OTHER +/-" at 315.835,114.576 h1.52
  text "DRILLING:" at 287.87,111.258 h1.52
  text "NC_DRILL FILES" at 332.599,108.586 h1.52
  text "REFERENCE:" at 289.769,108.486 h1.52
  text "X" at 306.463,108.484 h1.52
  text "AS SHOWN" at 310.984,108.486 h1.52
  text "X" at 329.348,108.486 h1.52
  text "OTHER" at 340.168,104.873 h1.52
  text "PTH COPPER THICKNESS:" at 289.761,104.783 h1.52
  text "X" at 318.697,104.783 h1.52
  text "20-30 um" at 321.948,104.783 h1.52
  text "BOARD FINISH:" at 287.87,101.034 h1.52
  text "SILKSCREEN:" at 291.812,98.237 h1.52
  text "X" at 316.14,98.237 h1.52
  text "TOP" at 319.112,98.237 h1.52
  text "X" at 329.094,98.237 h1.52
  text "BOTTOM" at 332.091,98.237 h1.52
  text "SILKSCREEN COLOR:" at 291.812,94.295 h1.52
  text "X" at 316.115,94.295 h1.52
  text "WHITE" at 319.112,94.295 h1.52
  text "OTHER" at 332.091,94.295 h1.52
  text "X" at 319.442,90.652 h1.52
  text "GREEN" at 322.439,90.652 h1.52
  text "OTHER" at 338.136,90.652 h1.52
  text "SOLDER RESIST COLOR:" at 291.812,90.477 h1.52
  text "X" at 319.442,86.734 h1.52
  text "MATTE" at 322.439,86.734 h1.52
  text "SEMI-GLOSS" at 338.125,86.717 h1.52
  text "IMMERSION GOLD (ENIG)" at 314.819,82.345 h1.52
  text "ENEPIG" at 348.793,82.162 h1.52
  text "SURFACE FINISH:" at 287.87,82.136 h1.52
  text "X" at 310.298,82.136 h1.52
  text "IMM. TIN/SILVER OR EQUIV" at 296.24,78.649 h1.52
  text "OTHER" at 332.599,78.549 h1.52
  text "ARRAY/PANEL:" at 287.87,74.602 h1.52
  text "CUT AND TRIM PER M1 BOARD OUTLINE" at 314.819,74.393 h1.52
  text "N.C. ROUTE" at 314.819,70.94 h1.52
  text "X" at 332.295,70.94 h1.52
  text "V. SCORE" at 336.816,70.94 h1.52
  text "CERTIFICATION:" at 287.87,67.66 h1.52
  text "MATERIALS AND WORKMANSHIP FOR ALL PCBS" at 306.285,67.66 h1.52
  text "TO MEET OR EXCEED THE REQUIREMENTS OF:" at 306.285,65.271 h1.52
  text "X" at 297.078,62.003 h1.52
  text "ANSI IPC-A-600F CLASS ->" at 300.329,62.003 h1.52
  text "X" at 342.188,62.003 h1.52
  text "2" at 344.982,62.003 h1.52
  text "1" at 336.981,61.965 h1.52
  text "3" at 353.973,61.965 h1.52
  text "X" at 317.702,58.252 h1.52
  text "RoHS" at 320.953,58.252 h1.52
  text "OTHER" at 337.321,58.252 h1.52
  text "PER ORDER" at 347.407,58.252 h1.52
  text "ALL BOARDS MUST MEET OR EXCEED UL94-V0 REQUIREMENTS." at 288.569,54.345 h1.52
  text "PCB MUST BEAR THE UL94V-0 UL REGISTERED MATERIAL ID NUMBER" at 288.569,51.397 h1.52
  text "ADDITIONAL REQUIREMENTS:" at 287.87,47.094 h1.52
  text "MICROSECTION:" at 289.769,44.373 h1.52
  text "YES" at 312.775,44.373 h1.52
  text "REQUIRED" at 334.657,40.707 h1.52
  text "BARE BOARD ELEC. TEST:" at 289.769,40.634 h1.52
  text "NONE" at 322.935,40.634 h1.52
  text "X" at 331.66,40.634 h1.52
  text "PER ORDER" at 349.693,40.634 h1.52
  text "XX MIL VIAS REQUIRE NON-CONDUCTIVE FILL AND PLANARIZE" at 294.04,35.428 h1.5
  text "XX MIL VIAS REQUIRE CONDUCTIVE FILL AND PLANARIZE" at 294.243,32.787 h1.52
  text "OUTER XX MIL TRACES REQUIRE 50 OHM SINGLE-ENDED IMPEDANCE" at 294.218,28.637 h1.47
  text "LAYER 2 & 3 (INNER LAYERS) XX MIL WIDE, XX MIL SPACE / TRACES REQUIRE 100 OHM DIFFERENTIAL IMPEDANCE" at 294.015,22.65 h1.52
  text ".Layer_Name" at 14.656,-21.806 h1.52
M11 Gerber Information:
  lines w0.254: -7.417,-23.626 160.223,-23.626 ; -7.417,-18.462 160.274,-18.462 ; -7.417,-13.297 -7.417,-28.791 94.31,-28.791 160.274,-28.791 160.274,-13.297 -7.404,-13.297 -7.404,-28.791 32.614,-28.791 ; 55.194,-28.791 55.194,-13.297 ; 87.376,-18.462 87.376,-13.297 ; 108.712,-18.462 108.712,-13.297 ; 124.511,-28.956 124.511,-23.804
  text "ALL ARTWORK VIEWED FROM TOP SIDE" at -5.804,-16.654 h1.52
  text "BOARD #:" at 57.099,-16.654 h1.52
  text ".PRJ_Number" at 70.955,-16.654 h1.52
  text "REV:" at 92.405,-16.654 h1.52
  text ".PCB_Rev" at 99.809,-16.654 h1.52
  text "SVN REV:" at 113.69,-16.654 h1.52
  text ".VersionControl_RevNumber" at 126.543,-16.654 h1.52
  text "LAYER NAME =" at -5.804,-21.806 h1.52
  text "TID #:" at 57.099,-21.819 h1.52
  text ".TID" at 70.955,-21.819 h1.52
  text "PLOT NAME =" at -5.804,-27.034 h1.52
  text ".plot_File_Name" at 14.656,-27.034 h1.52
  text "GENERATED    :" at 57.15,-27.034 h1.52
  text ".Print_Date" at 79.235,-27.034 h1.52
  text ".Print_Time" at 97.752,-27.034 h1.52
  text "TEXAS INSTRUMENTS" at 129.87,-27.034 h1.52
M12 Stackup:
  drawing of 399 lines, arcs and shapes, not listed
  text "Layer" at 249.469,200.023 h1.52
  text "Name" at 259.88,200.023 h1.52
  text "Material" at 293.653,200.023 h1.52
  text "Thickness" at 308.889,200.023 h1.52
  text "Constant" at 325.395,200.023 h1.52
  text "Board Layer Stack" at 339.869,200.023 h1.52
  text "Top Overlay" at 259.88,196.975 h1.52
  text "Top Solder" at 259.88,193.927 h1.52
  text "SM-001" at 293.653,193.927 h1.52
  text "1.00mil" at 308.889,193.927 h1.52
  text "4" at 325.395,193.927 h1.52
  text "Top Surface Finish" at 259.88,190.879 h1.52
  text "PbSn" at 293.653,190.879 h1.52
  text "0.79mil" at 308.889,190.879 h1.52
  text "1" at 249.469,187.831 h1.52
  text "Top Layer" at 259.88,187.831 h1.52
  text "CF-004" at 293.653,187.831 h1.52
  text "1.38mil" at 308.889,187.831 h1.52
  text "Dielectric 1" at 259.88,184.783 h1.52
  text "PP-017" at 293.653,184.783 h1.52
  text "5.10mil" at 308.889,184.783 h1.52
  text "4.3" at 325.395,184.783 h1.52
  text "Dielectric 2" at 259.88,181.735 h1.52
  text "PP-017" at 293.653,181.735 h1.52
  text "5.10mil" at 308.889,181.735 h1.52
  text "4.3" at 325.395,181.735 h1.52
  text "2" at 249.469,178.687 h1.52
  text "Int1 (GND)" at 259.88,178.687 h1.52
  text "CF-004" at 293.653,178.687 h1.52
  text "1.38mil" at 308.889,178.687 h1.52
  text "Dielectric 3" at 259.88,175.639 h1.52
  text "Core-039" at 293.653,175.639 h1.52
  text "28.00mil" at 308.889,175.639 h1.52
  text "4.8" at 325.395,175.639 h1.52
  text "3" at 249.469,172.591 h1.52
  text "Int2 (PWR)" at 259.88,172.591 h1.52
  text "CF-004" at 293.653,172.591 h1.52
  text "1.38mil" at 308.889,172.591 h1.52
  text "Dielectric 4" at 259.88,169.543 h1.52
  text "PP-017" at 293.653,169.543 h1.52
  text "5.10mil" at 308.889,169.543 h1.52
  text "4.3" at 325.395,169.543 h1.52
  text "Dielectric 5" at 259.88,166.495 h1.52
  text "PP-017" at 293.653,166.495 h1.52
  text "5.10mil" at 308.889,166.495 h1.52
  text "4.3" at 325.395,166.495 h1.52
  text "4" at 249.469,163.447 h1.52
  text "Bottom Layer" at 259.88,163.447 h1.52
  text "CF-004" at 293.653,163.447 h1.52
  text "1.38mil" at 308.889,163.447 h1.52
  text "Bottom Surface Finish" at 259.88,160.399 h1.52
  text "PbSn" at 293.653,160.399 h1.52
  text "0.79mil" at 308.889,160.399 h1.52
  text "Bottom Solder" at 259.88,157.351 h1.52
  text "SM-001" at 293.653,157.351 h1.52
  text "1.00mil" at 308.889,157.351 h1.52
  text "4" at 325.395,157.351 h1.52
  text "Bottom Overlay" at 259.88,154.303 h1.52
  text ".Layer_Name" at 14.656,-21.806 h1.52
M13 Component Bodies Top:
  text ".Layer_Name" at 14.656,-21.806 h1.52
M14 Component Bodies Bottom:
  text ".Layer_Name" at 14.656,-21.806 h1.52
M15 Courtyards Top:
  text ".Layer_Name" at 14.656,-21.806 h1.52
M16 Courtyards Bottom:
  text ".Layer_Name" at 14.656,-21.806 h1.52
Drill Drawing:
  circle w0.254: c136.238,70.943 r0.702
  circle w0.254: c136.238,64.628 r0.421
  circle w0.254: c136.238,64.628 r0.702
  lines w0.254: 135.537,61.12 135.887,61.12 136.238,60.769 136.589,61.12 136.94,61.12 136.589,61.471 136.94,61.822 136.589,61.822 136.238,62.172 135.887,61.822 135.537,61.822 135.887,61.471 135.537,61.12 ; 135.537,67.084 136.94,67.084 136.94,68.487 135.537,68.487 135.537,67.084 ; 135.537,73.399 135.537,73.75 135.887,74.101 135.537,74.452 135.537,74.803 135.887,74.803 136.238,74.452 136.589,74.803 136.94,74.803 136.94,74.452 136.589,74.101 136.94,73.75 136.94,73.399 136.589,73.399 136.238,73.75 135.887,73.399 135.537,73.399 ; 135.537,76.557 136.238,76.908 136.94,76.557 136.589,77.258 136.94,77.96 136.238,77.609 135.537,77.96 135.887,77.258 135.537,76.557 ; 135.537,81.118 136.94,81.118 136.238,79.714 135.537,81.118 ; 135.537,83.223 135.887,83.223 135.887,82.872 136.589,82.872 136.589,83.223 136.94,83.223 136.94,83.924 136.589,83.924 136.589,84.275 135.887,84.275 135.887,83.924 135.537,83.924 135.537,83.223
  lines w0.305: 134.264,59.822 216.356,59.822 ; 134.264,85.082 216.356,85.082 ; 142.845,56.664 142.845,88.24 ; 151.281,56.664 151.281,88.24 ; 167.452,56.664 167.452,88.24 ; 174.034,56.664 174.034,88.24 ; 183.565,56.664 183.565,88.24 ; 201.967,56.664 201.967,88.24 ; 134.264,56.664 216.356,56.664 216.356,88.24 134.264,88.24 134.264,56.664
  text "Symbol" at 136.159,86.029 h1.83
  text "Quantity" at 143.792,86.029 h1.83
  text "Finished Hole Size" at 152.228,86.029 h1.83
  text "Plated" at 168.399,86.029 h1.83
  text "Hole Type" at 174.981,86.029 h1.83
  text "Drill Layer Pair" at 184.512,86.029 h1.83
  text "Hole Tolerance" at 202.914,86.029 h1.83
  text "5" at 143.792,82.872 h1.52
  text "47.24mil (1.200mm)" at 152.228,82.872 h1.52
  text "NPTH" at 168.399,82.872 h1.52
  text "Round" at 174.981,82.872 h1.52
  text "Top Layer - Bottom Layer" at 184.512,82.872 h1.52
  text "4" at 143.792,79.714 h1.52
  text "125.00mil (3.175mm)" at 152.228,79.714 h1.52
  text "NPTH" at 168.399,79.714 h1.52
  text "Round" at 174.981,79.714 h1.52
  text "Top Layer - Bottom Layer" at 184.512,79.714 h1.52
  text "9" at 143.792,76.557 h1.52
  text "7.87mil (0.200mm)" at 152.228,76.557 h1.52
  text "PTH" at 168.399,76.557 h1.52
  text "Round" at 174.981,76.557 h1.52
  text "Top Layer - Bottom Layer" at 184.512,76.557 h1.52
  text "286" at 143.792,73.399 h1.52
  text "11.81mil (0.300mm)" at 152.228,73.399 h1.52
  text "PTH" at 168.399,73.399 h1.52
  text "Round" at 174.981,73.399 h1.52
  text "Top Layer - Bottom Layer" at 184.512,73.399 h1.52
  text "1" at 143.792,70.242 h1.52
  text "25.00mil (0.635mm)" at 152.228,70.242 h1.52
  text "PTH" at 168.399,70.242 h1.52
  text "Round" at 174.981,70.242 h1.52
  text "Top Layer - Bottom Layer" at 184.512,70.242 h1.52
  text "11" at 143.792,67.084 h1.52
  text "27.56mil (0.700mm)" at 152.228,67.084 h1.52
  text "PTH" at 168.399,67.084 h1.52
  text "Round" at 174.981,67.084 h1.52
  text "Top Layer - Bottom Layer" at 184.512,67.084 h1.52
  text "9" at 143.792,63.927 h1.52
  text "40.00mil (1.016mm)" at 152.228,63.927 h1.52
  text "PTH" at 168.399,63.927 h1.52
  text "Round" at 174.981,63.927 h1.52
  text "Top Layer - Bottom Layer" at 184.512,63.927 h1.52
  text "40" at 143.792,60.769 h1.52
  text "45.28mil (1.150mm)" at 152.228,60.769 h1.52
  text "PTH" at 168.399,60.769 h1.52
  text "Round" at 174.981,60.769 h1.52
  text "Top Layer - Bottom Layer" at 184.512,60.769 h1.52
  text "365 Total" at 143.792,57.612 h1.52
  text ".Layer_Name" at 14.656,-21.806 h1.52
M17 Embedded Cavity:
  text ".Layer_Name" at 14.656,-21.806 h1.52
M18 Embedded Assembly:
  text ".Layer_Name" at 14.656,-21.806 h1.52
M19 Embedded Keepout:
  text ".Layer_Name" at 14.656,-21.806 h1.52

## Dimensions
0,-10.16 to 25.4,-10.16 on M2 Board Dimensions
